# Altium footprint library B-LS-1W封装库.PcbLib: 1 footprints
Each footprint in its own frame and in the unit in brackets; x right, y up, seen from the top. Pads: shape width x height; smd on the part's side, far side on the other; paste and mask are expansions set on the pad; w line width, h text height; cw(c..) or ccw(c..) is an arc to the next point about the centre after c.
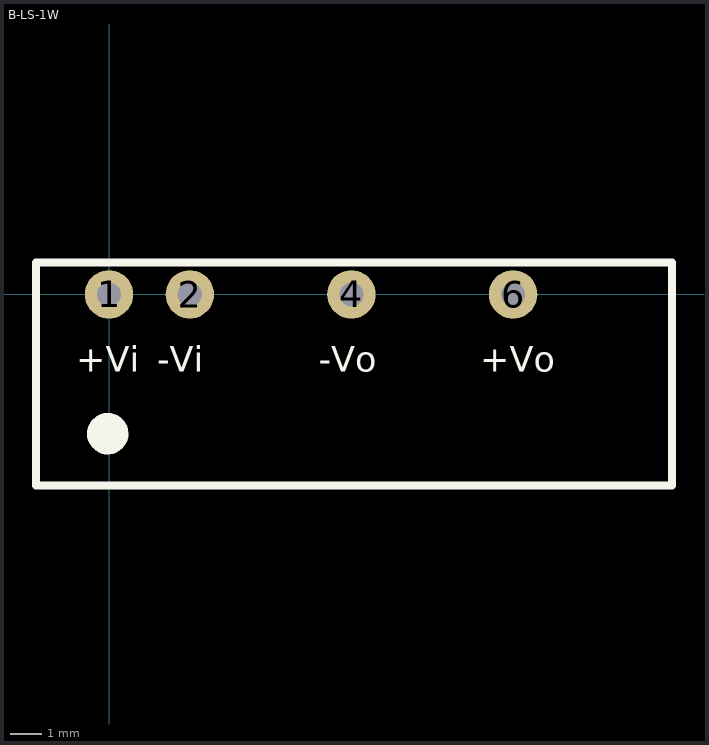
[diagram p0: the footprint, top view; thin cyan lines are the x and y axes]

## B-LS-1W [mil]
pads (4):
  round 60 hole 30: 1(0,0) 2(100,0) 4(300,0) 6(500,0)
Top Overlay:
  lines w10: -90.55,-236.22 -90.55,39.37 696.85,39.37 696.85,-236.22 -90.55,-236.22
  lines w27.56: 10,-170 ccw(c-1.58,-172.32) 10.23,-172.32
  text "+Vi" at -40.55,-95.63 h31.5
  text "-Vi" at 59.45,-95.63 h31.5
  text "-Vo" at 259.45,-95.63 h31.5
  text "+Vo" at 459.45,-95.63 h31.5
